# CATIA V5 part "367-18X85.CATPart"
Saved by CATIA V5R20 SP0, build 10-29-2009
Part number: 367-18X85
Definition: NONE
Nomenclature: 367-18X85
Source: Unknown
Description: 367-18X85
Bounding box of the stored display mesh (mm): x 0 to 85, y -14 to 14, z -14 to 14
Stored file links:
  C:\Users\Utente\Desktop\IO LAVORO\3D X SITO CF\X SITO\PLASTICA\3D files 367\367-18X85.CATPart
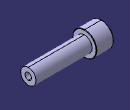
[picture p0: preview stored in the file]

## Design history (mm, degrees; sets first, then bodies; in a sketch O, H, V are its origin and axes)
Body1 "367-18X85" (main body)
  Solid1: solid without history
